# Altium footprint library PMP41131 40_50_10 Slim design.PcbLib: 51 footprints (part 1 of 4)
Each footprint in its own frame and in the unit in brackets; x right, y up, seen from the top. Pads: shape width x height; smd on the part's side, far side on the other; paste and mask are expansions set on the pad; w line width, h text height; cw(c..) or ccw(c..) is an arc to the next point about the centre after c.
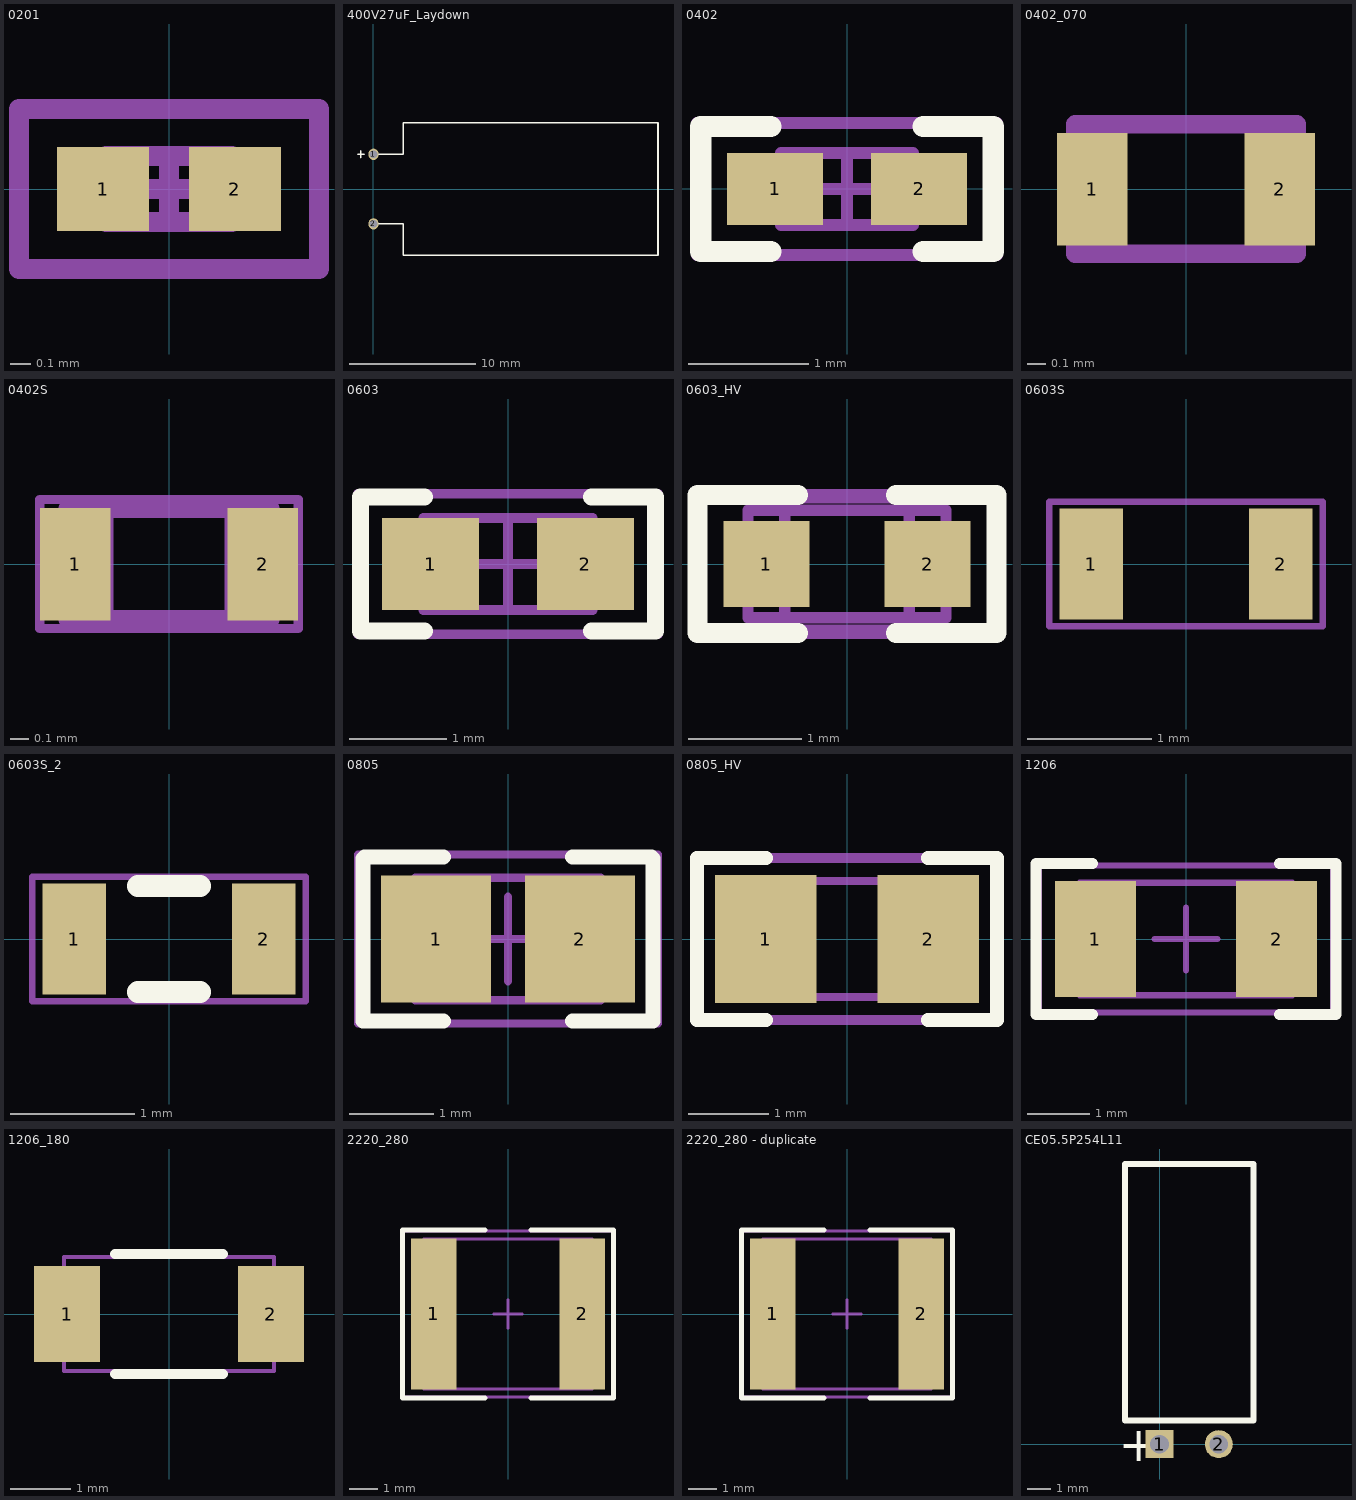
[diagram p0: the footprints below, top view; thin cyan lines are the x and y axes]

## 0201 [mm] "Data from Kemet datasheet CC101_COM dated 7/28/11"
height 0.26
pads (2):
  rect 0.46x0.42 smd mask+0.048: 1(-0.33,0) 2(0.33,0)
Mechanical 5:
  lines w0.1: -0.75,-0.4 0.75,-0.4 0.75,0.4 -0.75,0.4 -0.75,-0.4
  text ".Designator" at -0.66,-0.178 h0.36
Mechanical 13:
  lines w0.1: -0.215,-0.165 -0.215,0.165 ; 0.215,-0.165 0.215,0.165 ; -0.315,-0.165 -0.315,0.165 0.315,0.165 0.315,-0.165 -0.315,-0.165
Mechanical 15:
  lines w0.1: -0.165,0 0.165,0 ; 0,-0.165 0,0.165 ; -0.75,-0.4 -0.75,0.4 0.75,0.4 0.75,-0.4 -0.75,-0.4
3D body: height 0.26, standoff 0, extent -0.314,-0.164 -0.216,0.164
3D body: height 0.26, standoff 0, extent -0.214,-0.164 0.214,0.164
3D body: height 0.26, standoff 0, extent 0.216,-0.164 0.314,0.164

## 400V27uF_Laydown [mm]
pads (2):
  oval 0.8x0.9 hole 0.6: 1(0,2.75) 2(0,-2.75)
Top Overlay:
  lines w0.127: -1.223,2.747 -0.743,2.747 ; -0.993,2.497 -0.993,3.027 ; 0,-2.75 2.37,-2.75 2.37,-5.23 22.5,-5.23 22.5,5.24 ; 0,2.75 2.37,2.75 2.37,5.25 22.5,5.25
3D body: height 5, standoff -5, extent 2.395,-4.895 22.395,5.105
3D body: height 0.51, standoff 0, extent -0.064,-5.294 22.564,5.314

## 0402 [mm] "0402 from SM-752 data"
height 0.6
pads (2):
  rect 0.8x0.6 smd: 1(-0.6,0) 2(0.6,0)
Top Overlay:
  lines w0.178: -0.635,-0.521 -1.219,-0.521 -1.219,0.521 -0.635,0.521 ; 0.635,-0.521 1.219,-0.521 1.219,0.521 0.635,0.521
Mechanical 5:
  lines w0.1: -1.25,-0.55 1.25,-0.55 1.25,0.55 -1.25,0.55 -1.25,-0.55
  text ".Designator" at -1.117,-0.305 h0.61
Mechanical 13:
  lines w0.1: -0.35,-0.3 -0.35,0.3 ; 0.35,-0.3 0.35,0.3 ; -0.55,-0.3 -0.55,0.3 0.55,0.3 0.55,-0.3 -0.55,-0.3
Mechanical 15:
  lines w0.1: -0.3,0 0.3,0 ; 0,-0.3 0,0.3 ; -1.25,-0.55 -1.25,0.55 1.25,0.55 1.25,-0.55 -1.25,-0.55
3D body: height 0.6, standoff 0, extent -0.549,-0.299 -0.351,0.299
3D body: height 0.6, standoff 0, extent -0.349,-0.299 0.349,0.299
3D body: height 0.6, standoff 0, extent 0.351,-0.299 0.549,0.299

## 0402_070 [mil] "SMD, 2-Leads, Body 1.2x0.7mm, Height 0.7mm"
height 27.56
pads (2):
  rect 15x24 smd: 1(-20,0) 2(20,0)
Mechanical 5:
  lines w3.94: -23.62,-13.78 -23.62,13.78 23.62,13.78 23.62,-13.78 -23.62,-13.78
  text ".Designator" at -21.65,-5.91 h12
3D body: height 27.56, standoff 0, extent 13.78,-13.78 23.62,13.78
3D body: height 27.56, standoff 0, extent -23.62,-13.78 -13.78,13.78
3D body: height 27.56, standoff 0, extent -13.78,-13.78 13.78,13.78

## 0402S [mil] "Based on C0402S footprint from PADS legacy"
height 23.62
pads (2):
  rect 15x24 smd: 1(-20,0) 2(20,0)
Mechanical 5:
  lines w1.97: -27.56,-13.78 27.56,-13.78 27.56,13.78 -27.56,13.78 -27.56,-13.78
  text ".Designator" at -21.65,-5.91 h12
Mechanical 13:
  lines w3.94: -13.78,-11.81 -13.78,11.81 ; 13.78,-11.81 13.78,11.81 ; -21.65,-11.81 -21.65,11.81 21.65,11.81 21.65,-11.81 -21.65,-11.81
3D body: height 23.62, standoff 0, extent -21.63,-11.79 -13.8,11.79
3D body: height 23.62, standoff 0, extent -13.76,-11.79 13.76,11.79
3D body: height 23.62, standoff 0, extent 13.8,-11.79 21.63,11.79

## 0603 [mm] "0603 from SM-752 data"
height 1
pads (2):
  rect 1x0.95 smd: 1(-0.8,0) 2(0.8,0)
Top Overlay:
  lines w0.178: -0.864,-0.691 -1.524,-0.691 -1.524,0.693 -0.864,0.693 ; 0.864,-0.691 1.524,-0.691 1.524,0.693 0.864,0.693
Mechanical 5:
  lines w0.1: -1.55,-0.725 1.55,-0.725 1.55,0.725 -1.55,0.725 -1.55,-0.725
  text ".Designator" at -1.397,-0.381 h0.76
Mechanical 13:
  lines w0.1: -0.55,-0.475 -0.55,0.475 ; 0.55,-0.475 0.55,0.475 ; -0.875,-0.475 -0.875,0.475 0.875,0.475 0.875,-0.475 -0.875,-0.475
Mechanical 15:
  lines w0.1: -0.475,0 0.475,0 ; 0,-0.475 0,0.475 ; -1.55,-0.725 -1.55,0.725 1.55,0.725 1.55,-0.725 -1.55,-0.725
3D body: height 1, standoff 0, extent 0.551,-0.474 0.874,0.474
3D body: height 1, standoff 0, extent -0.549,-0.474 0.549,0.474
3D body: height 1, standoff 0, extent -0.874,-0.474 -0.551,0.474

## 0603_HV [mil] "Ernesto recommended land pattern.  26 mil between pads."
height 39.37
pads (2):
  rect 30x30 smd: 1(-28,0) 2(28,0)
Top Overlay:
  lines w7: -17,-24 -52,-24 -52,0 -52,24 -17,24 ; 17,-24 52,-24 52,0 52,24 17,24
Mechanical 5:
  lines w5: -52.17,-23.62 -52.17,23.62 52.17,23.62 52.17,-23.62 -52.17,-23.62
  text ".Designator" at -45.82,-12.5 h25
Mechanical 13:
  lines w3.94: -21.65,-18.7 -21.65,18.7 ; 21.65,-18.7 21.65,18.7 ; -34.45,-18.7 -34.45,18.7 34.45,18.7 34.45,-18.7 -34.45,-18.7
3D body: height 39.37, standoff 0, extent 21.67,-18.68 34.43,18.68
3D body: height 39.37, standoff 0, extent -21.63,-18.68 21.63,18.68
3D body: height 39.37, standoff 0, extent -34.43,-18.68 -21.67,18.68

## 0603S [mil]
height 39.37
pads (2):
  rect 20x35 smd: 1(-30,0) 2(30,0)
Mechanical 5:
  lines w1.97: -43.31,-19.68 -43.31,19.68 43.31,19.68 43.31,-19.68 -43.31,-19.68
  text ".Designator" at -32.48,-8.86 h18
3D body: height 39.37, standoff 0, extent 21.67,-18.68 34.43,18.68
3D body: height 39.37, standoff 0, extent -21.63,-18.68 21.63,18.68
3D body: height 39.37, standoff 0, extent -34.43,-18.68 -21.67,18.68

## 0603S_2 [mil]
pads (2):
  rect 20x35 smd: 1(-30,0) 2(30,0)
Top Overlay:
  lines w7: -9.84,-16.73 9.84,-16.73 ; -9.84,16.73 9.84,16.73
Mechanical 5:
  lines w1.97: -43.31,-19.68 -43.31,19.68 43.31,19.68 43.31,-19.68 -43.31,-19.68
  text ".Designator" at -32.48,-8.86 h18
3D body: height 39.37, standoff 0, extent 21.67,-18.68 34.43,18.68
3D body: height 39.37, standoff 0, extent -21.63,-18.68 21.63,18.68
3D body: height 39.37, standoff 0, extent -34.43,-18.68 -21.67,18.68

## 0805 [mm] "0805 from SM-752 data"
height 1.45
pads (2):
  rect 1.3x1.5 smd: 1(-0.85,0) 2(0.85,0)
Top Overlay:
  lines w0.178: -0.762,-0.968 -1.717,-0.968 -1.717,0.95 -1.699,0.968 -0.762,0.968 ; 0.762,-0.968 1.717,-0.968 1.717,0.95 1.699,0.968 0.762,0.968
Mechanical 5:
  lines w0.1: -1.775,-1 1.775,-1 1.775,1 -1.775,1 -1.775,-1
  text ".Designator" at -1.525,-0.425 h0.81
Mechanical 13:
  lines w0.1: -0.65,-0.725 -0.65,0.725 ; 0.65,-0.725 0.65,0.725 ; -1.1,-0.725 1.1,-0.725 1.1,0.725 -1.1,0.725 -1.1,-0.725
Mechanical 15:
  lines w0.1: -0.5,0 0.5,0 ; 0,-0.5 0,0.5 ; -1.775,-1 1.775,-1 1.775,1 -1.775,1 -1.775,-1
3D body: height 1.45, standoff 0, extent -1.099,-0.724 -0.651,0.724
3D body: height 1.45, standoff 0, extent -0.649,-0.724 0.649,0.724
3D body: height 1.45, standoff 0, extent 0.651,-0.724 1.099,0.724

## 0805_HV [mil] "0805 with 30mil clearance between pads"
height 57.09
pads (2):
  rect 50x63 smd: 1(-40,0) 2(40,0)
Top Overlay:
  lines w7: -40,-40 -74,-40 -74,0 -74,40 -40,40 ; 40,-40 74,-40 74,0 74,40 40,40
Mechanical 5:
  lines w5: -74,-40 74,-40 74,40 -74,40 -74,-40
  text ".Designator" at -64,-17 h35
Mechanical 13:
  lines w3.94: -25.59,-28.54 -25.59,28.54 ; 25.59,-28.54 25.59,28.54 ; -43.31,-28.54 43.31,-28.54 43.31,28.54 -43.31,28.54 -43.31,-28.54
3D body: height 57.09, standoff 0, extent -43.29,-28.52 -25.61,28.52
3D body: height 57.09, standoff 0, extent -25.57,-28.52 25.57,28.52
3D body: height 57.09, standoff 0, extent 25.61,-28.52 43.29,28.52

## 1206 [mm] "1206 from SM-752 data"
height 1.35
pads (2):
  rect 1.3x1.85 smd: 1(-1.45,0) 2(1.45,0)
Top Overlay:
  lines w0.178: -1.5,-1.21 -2.4,-1.21 -2.4,1.21 -1.5,1.21 ; 1.5,-1.21 2.4,-1.21 2.4,1.21 1.5,1.21
Mechanical 5:
  lines w0.1: -1.7,-0.9 -1.7,0.9 1.7,0.9 1.7,-0.9 -1.7,-0.9
  text ".Designator" at -1.475,-0.4 h0.81
Mechanical 13:
  lines w0.1: -1.2,-0.9 -1.2,0.9 ; 1.2,-0.9 1.2,0.9 ; -1.7,-0.9 -1.7,0.9 1.7,0.9 1.7,-0.9 -1.7,-0.9
Mechanical 15:
  lines w0.1: -0.5,0 0.5,0 ; 0,-0.5 0,0.5 ; -2.35,-1.175 -2.35,1.175 2.35,1.175 2.35,-1.175 -2.35,-1.175
3D body: height 1.35, standoff 0, extent 1.201,-0.899 1.699,0.899
3D body: height 1.35, standoff 0, extent -1.199,-0.899 1.199,0.899
3D body: height 1.35, standoff 0, extent -1.699,-0.899 -1.201,0.899

## 1206_180 [mm] "1206_180"
height 1.8
pads (2):
  rect 1.1x1.6 smd: 1(-1.7,0) 2(1.7,0)
Top Overlay:
  lines w0.17: -0.9,-1 0.9,-1 ; -0.9,1 0.9,1
Mechanical 5:
  lines w0.07: -1.75,-0.95 1.75,-0.95 1.75,0.95 -1.75,0.95 -1.75,-0.95
  text ".Designator" at -1.5,-0.4 h0.81
3D body: height 1.8, standoff 0, extent -1.749,-0.949 -1.301,0.949
3D body: height 1.8, standoff 0, extent -1.299,-0.949 1.299,0.949
3D body: height 1.8, standoff 0, extent 1.301,-0.949 1.749,0.949

## 2220_280 [mm] "Chip Capacitor, Body 5.7x5.0mm, IPC Medium Density"
height 2.8
pads (2):
  rect 1.6x5.3 smd: 1(-2.6,0) 2(2.6,0)
Top Overlay:
  lines w0.178: -0.811,-2.939 -3.693,-2.939 -3.693,2.939 -0.811,2.939 ; 0.811,-2.939 3.693,-2.939 3.693,2.939 0.811,2.939
Mechanical 5:
  lines w0.1: -2.95,-2.625 2.95,-2.625 2.95,2.625 -2.95,2.625 -2.95,-2.625
  text ".Designator" at -1.875,-0.5 h1.02
Mechanical 13:
  lines w0.1: -2.75,-2.625 -2.75,2.625 ; 2.75,-2.625 2.75,2.625 ; -2.95,-2.625 -2.95,2.625 2.95,2.625 2.95,-2.625 -2.95,-2.625
Mechanical 15:
  lines w0.1: -0.5,0 0.5,0 ; 0,-0.5 0,0.5 ; -3.65,-2.9 -3.65,2.9 3.65,2.9 3.65,-2.9 -3.65,-2.9
3D body: height 2.8, standoff 0, extent -2.949,-2.624 -2.751,2.624
3D body: height 2.8, standoff 0, extent -2.749,-2.624 2.749,2.624
3D body: height 2.8, standoff 0, extent 2.751,-2.624 2.949,2.624

## 2220_280 - duplicate [mm] "Chip Capacitor, Body 5.7x5.0mm, IPC Medium Density"
height 2.8
pads (2):
  rect 1.6x5.3 smd: 1(-2.6,0) 2(2.6,0)
Top Overlay:
  lines w0.178: -0.811,-2.939 -3.693,-2.939 -3.693,2.939 -0.811,2.939 ; 0.811,-2.939 3.693,-2.939 3.693,2.939 0.811,2.939
Mechanical 5:
  lines w0.1: -2.95,-2.625 -2.95,2.625 2.95,2.625 2.95,-2.625 -2.95,-2.625
  text ".Designator" at -1.875,-0.5 h1.02
Mechanical 13:
  lines w0.1: -2.75,-2.625 -2.75,2.625 ; 2.75,-2.625 2.75,2.625 ; -2.95,-2.625 2.95,-2.625 2.95,2.625 -2.95,2.625 -2.95,-2.625
Mechanical 15:
  lines w0.1: -0.5,0 0.5,0 ; 0,-0.5 0,0.5 ; -3.65,-2.9 3.65,-2.9 3.65,2.9 -3.65,2.9 -3.65,-2.9
3D body: height 2.8, standoff 0, extent 2.751,-2.624 2.949,2.624
3D body: height 2.8, standoff 0, extent -2.749,-2.624 2.749,2.624
3D body: height 2.8, standoff 0, extent -2.949,-2.624 -2.751,2.624

## CE05.5P254L11 [mm]
height 1.1
pads (2):
  rect 1.2x1.2 hole 0.8: 1(0,0)
  round 1.2 hole 0.8: 2(2.54,0)
Top Overlay:
  lines w0.254: -1.48,1.016 -1.48,12.016 4.02,12.016 4.02,1.016 -1.48,1.016
  text "+" at -1.753,-0.737 h1.5
Bottom Overlay:
  circle w0.2: c2.54,0 r0.85
  lines w0.2: -0.849,-0.849 -0.849,0.85 0.849,0.85 0.849,-0.849 -0.849,-0.849
3D body: height 0.51, standoff 0, extent -1.48,1.016 4.02,12.016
